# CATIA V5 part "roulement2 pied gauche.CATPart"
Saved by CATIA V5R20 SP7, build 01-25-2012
Part number: roulement 2 pied gauche
Bounding box of the stored display mesh (mm): x 10.048 to 24.056, y -79 to -65, z 47.224 to 58.487
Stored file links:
  F:\Travaux\Modélisations\CFAO_2011\CFAO_2011_MMS\CFAO_2011_MMS_DONE\CFAO_2011_MMS_jboiteux\Catia\roulement2 pied gauche.CATPart
  U:\finthinkmotion\stepper.CATProduct
  F:\Travaux\Modélisations\CFAO_2011\CFAO_2011_MMS\CFAO_2011_MMS_DONE\CFAO_2011_MMS_jboiteux\Catia\support pied gauche.CATPart
  F:\Travaux\Modélisations\CFAO_2011\CFAO_2011_MMS\CFAO_2011_MMS_DONE\CFAO_2011_MMS_jboiteux\Catia\bati.CATPart
  F:\Travaux\Modélisations\CFAO_2011\CFAO_2011_MMS\CFAO_2011_MMS_DONE\CFAO_2011_MMS_jboiteux\Catia\Part1.CATPart
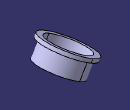
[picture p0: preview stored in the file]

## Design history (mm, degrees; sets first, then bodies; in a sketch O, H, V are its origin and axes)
Parameters
  rayontube = 9 mm {= External.royontubebati}
External parameters (linked from other documents)
  External.royontubebati = 9 mm
Set1
  DatumSurface1: linked copy from another document
  DatumCurve1: linked copy from another document
  DatumSurface2: linked copy from another document
  Point1: linked copy from another document
Body1 (main body)
  Sketch1 on face of DatumSurface1, origin (-19.2828, 0, 33.3987), H (0, 1, 0), V (0.866, 0, 0.5)
    projected circle E1 centre (-72, 41.4454) radius 7 from edge of DatumCurve1
    circle A1 centre (-72, 41.4454) radius 5.5
    point P1 (-72, 41.4454)
    reference projected point E2 (-72, 41.4454) from Point1
    radius A1 = 5.5 {= rayontube *5/9+0.5mm}
    coincidence: E2 P1
  Pad1: profile Sketch1, direction (-0.5, 0, 0.866), length 1
  Sketch2 on start face of Pad1, origin (-19.2828, 0, 33.3987), H (0, 1, 0), V (0.866, 0, 0.5)
    projected circle E1 centre (-72, 41.4454) radius 5.5 from edge [start face of Pad1 | face of Pad1 from Sketch1.A1]
    circle A1 centre (-72, 41.4454) radius 6
    point P1 (-72, 41.4454)
    reference projected point E2 (-72, 41.4454) from Point1
    radius A1 = 6 {= rayontube *5/9+1mm}
    coincidence: E2 P1
  Pad2: profile Sketch2, direction (0.5, 0, -0.866), length 4.5 {= rayontube /2}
